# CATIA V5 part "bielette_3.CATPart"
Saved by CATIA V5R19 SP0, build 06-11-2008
Part number: skl_bielette_3
Publications: "axe_pivot_bielette3_levier", "axe_pivot_bielette3_sabot2", "Plan.1", "Droite.1"
Bounding box of the stored display mesh (mm): x -110 to 0, y 355 to 410, z -20 to 20
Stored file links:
  C:\Users\Thibaud\Desktop\IFMA\thinkmotion\IAO\modele_catia\squelette\bielette_3.CATPart
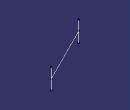
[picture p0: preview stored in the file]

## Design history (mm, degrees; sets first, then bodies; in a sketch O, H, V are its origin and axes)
Body1 (main body)
  Point1 "Point.2": stored without definition
  Point2: stored without definition
  Line1: type PtPt, SecondPoint Point2, FirstPoint Point1
  Plane1: stored without definition
  Point3: stored without definition
  Line2 "axe_pivot_bielette3_sabot2": type Normal, RefSkin Plane1, Start -20, End 20, RefPoint Point3
  Plane2: stored without definition
  Point4 "Point.2": stored without definition
  Line3 "axe_pivot_bielette3_levier": type Normal, RefSkin Plane2, Start -20, End 20, RefPoint Point4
